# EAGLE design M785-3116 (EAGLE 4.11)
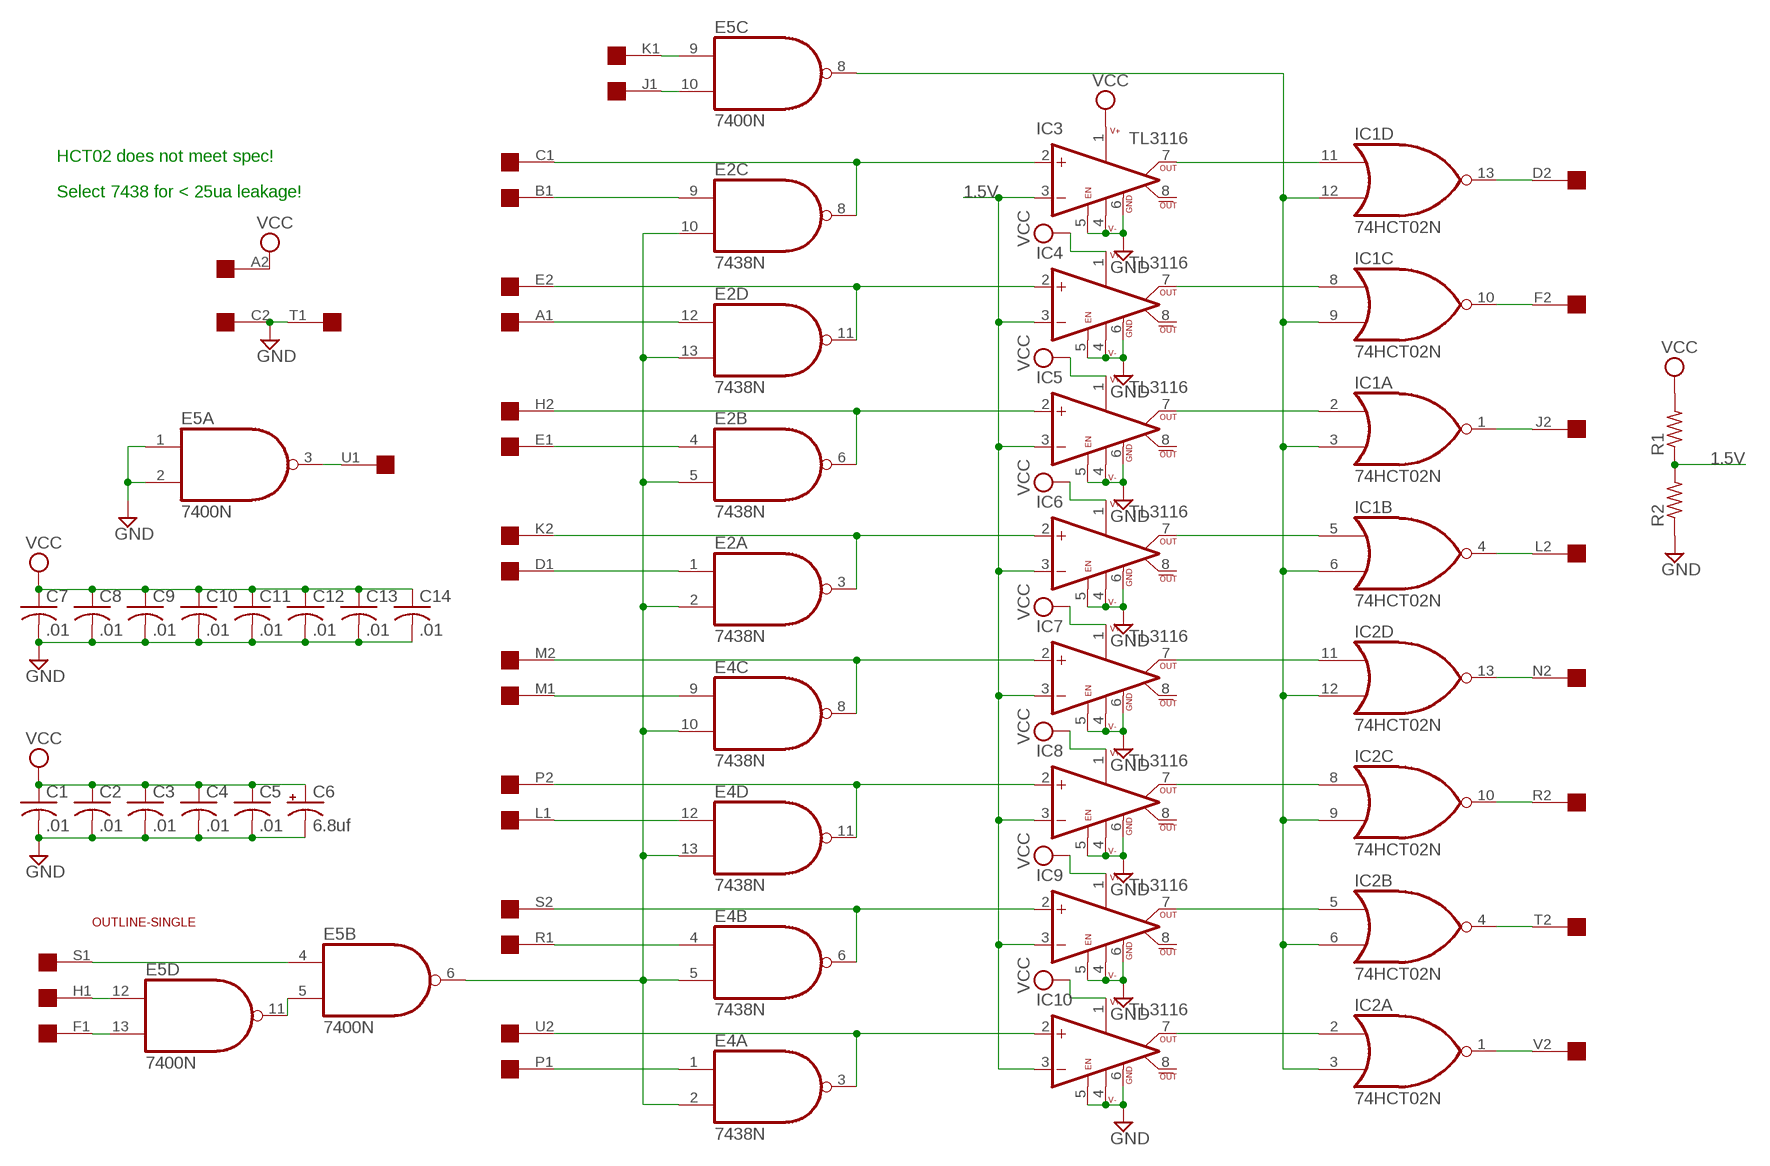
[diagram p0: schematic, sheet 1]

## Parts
C1  .01  C-US050-025X075  [C050-025X075]
C2  .01  C-US050-025X075  [C050-025X075]
C3  .01  C-US050-025X075  [C050-025X075]
C4  .01  C-US050-025X075  [C050-025X075]
C5  .01  C-US050-025X075  [C050-025X075]
C6  6.8uf  CPOL-USE15-5AXIAL  [E15-5]
C7  .01  C-US050-025X075  [C050-025X075]
C8  .01  C-US050-025X075  [C050-025X075]
C9  .01  C-US050-025X075  [C050-025X075]
C10  .01  C-US050-025X075  [C050-025X075]
C11  .01  C-US050-025X075  [C050-025X075]
C12  .01  C-US050-025X075  [C050-025X075]
C13  .01  C-US050-025X075  [C050-025X075]
C14  .01  C-US050-025X075  [C050-025X075]
E2  7438N  [DIL14]
E4  7438N  [DIL14]
E5  7400N  [DIL14]
IC1  74HCT02N  7402N  [DIL14]
IC2  74HCT02N  7402N  [DIL14]
IC3  TL3116  LT1016CN  [DIL08]
IC4  TL3116  LT1016CN  [DIL08]
IC5  TL3116  LT1016CN  [DIL08]
IC6  TL3116  LT1016CN  [DIL08]
IC7  TL3116  LT1016CN  [DIL08]
IC8  TL3116  LT1016CN  [DIL08]
IC9  TL3116  LT1016CN  [DIL08]
IC10  TL3116  LT1016CN  [DIL08]
R1  R-US_0207/10  [0207/10]
R2  R-US_0207/10  [0207/10]
U$1  SINGLE  [EDGE-CON2]
U$2  OUTLINE-SINGLE  [SINGLE]

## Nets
1.5V: IC3.3(-IN) IC4.3(-IN) IC5.3(-IN) IC6.3(-IN) IC7.3(-IN) IC8.3(-IN) IC9.3(-IN) IC10.3(-IN) R1.1 R2.2
GND: C1.2 C2.2 C3.2 C4.2 C5.2 C6.- C7.2 C8.2 C9.2 C10.2 C11.2 C12.2 C13.2 C14.2 E5.1(A:I0) E5.2(A:I1) IC3.4(V-) IC3.5(LA_EN) IC3.6(GND) IC4.4(V-) IC4.5(LA_EN) IC4.6(GND) IC5.4(V-) IC5.5(LA_EN) IC5.6(GND) IC6.4(V-) IC6.5(LA_EN) IC6.6(GND) IC7.4(V-) IC7.5(LA_EN) IC7.6(GND) IC8.4(V-) IC8.5(LA_EN) IC8.6(GND) IC9.4(V-) IC9.5(LA_EN) IC9.6(GND) IC10.4(V-) IC10.5(LA_EN) IC10.6(GND) R2.1 U$1.C2 U$1.T1
N$1: E5.8(C:O) IC1.3(A:I1) IC1.6(B:I1) IC1.9(C:I1) IC1.12(D:I1) IC2.3(A:I1) IC2.6(B:I1) IC2.9(C:I1) IC2.12(D:I1)
N$2: E2.2(A:I1) E2.5(B:I1) E2.10(C:I1) E2.13(D:I1) E4.2(A:I1) E4.5(B:I1) E4.10(C:I1) E4.13(D:I1) E5.6(B:O)
N$3: E4.8(C:O) IC7.2(+IN) U$1.M2
N$4: E4.3(A:O) IC10.2(+IN) U$1.U2
N$5: E4.1(A:I0) U$1.P1
N$6: E4.4(B:I0) U$1.R1
N$7: E4.6(B:O) IC9.2(+IN) U$1.S2
N$8: E4.12(D:I0) U$1.L1
N$9: E4.11(D:O) IC8.2(+IN) U$1.P2
N$10: E4.9(C:I0) U$1.M1
N$11: E2.8(C:O) IC3.2(+IN) U$1.C1
N$12: E2.9(C:I0) U$1.B1
N$13: E2.11(D:O) IC4.2(+IN) U$1.E2
N$14: E2.12(D:I0) U$1.A1
N$15: E2.6(B:O) IC5.2(+IN) U$1.H2
N$16: E2.4(B:I0) U$1.E1
N$17: E2.3(A:O) IC6.2(+IN) U$1.K2
N$18: E2.1(A:I0) U$1.D1
N$19: E5.9(C:I0) U$1.K1
N$20: E5.10(C:I1) U$1.J1
N$21: IC1.13(D:O) U$1.D2
N$22: IC1.10(C:O) U$1.F2
N$23: IC1.1(A:O) U$1.J2
N$24: IC1.4(B:O) U$1.L2
N$25: IC2.13(D:O) U$1.N2
N$26: IC2.10(C:O) U$1.R2
N$27: IC2.4(B:O) U$1.T2
N$28: IC2.1(A:O) U$1.V2
N$29: E5.4(B:I0) U$1.S1
N$30: E5.5(B:I1) E5.11(D:O)
N$31: E5.12(D:I0) U$1.H1
N$32: E5.13(D:I1) U$1.F1
N$33: E5.3(A:O) U$1.U1
N$34: IC1.11(D:I0) IC3.7(OUT)
N$35: IC2.11(D:I0) IC7.7(OUT)
N$36: IC1.5(B:I0) IC6.7(OUT)
N$37: IC1.2(A:I0) IC5.7(OUT)
N$38: IC1.8(C:I0) IC4.7(OUT)
N$39: IC2.5(B:I0) IC9.7(OUT)
N$40: IC2.8(C:I0) IC8.7(OUT)
N$43: IC2.2(A:I0) IC10.7(OUT)
VCC: C1.1 C2.1 C3.1 C4.1 C5.1 C6.+ C7.1 C8.1 C9.1 C10.1 C11.1 C12.1 C13.1 C14.1 IC3.1(V+) IC4.1(V+) IC5.1(V+) IC6.1(V+) IC7.1(V+) IC8.1(V+) IC9.1(V+) IC10.1(V+) R1.2 U$1.A2
Unconnected: IC3.8(OUT\) IC4.8(OUT\) IC5.8(OUT\) IC6.8(OUT\) IC7.8(OUT\) IC8.8(OUT\) IC9.8(OUT\) IC10.8(OUT\) U$1.B2 U$1.N1 U$1.V1

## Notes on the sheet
- HCT02 does not meet spec!
- Select 7438 for < 25ua leakage!

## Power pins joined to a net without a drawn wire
GND: E2.7(P:GND) E4.7(P:GND) E5.7(P:GND) IC1.7(P:GND) IC2.7(P:GND)
VCC: E2.14(P:VCC) E4.14(P:VCC) E5.14(P:VCC) IC1.14(P:VCC) IC2.14(P:VCC)

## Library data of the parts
C1-C5 C7-C14 = rcl:C-US: CAPACITOR, American symbol
C6 = rcl:CPOL-US: POLARIZED CAPACITOR, American symbol
E2 E4 = 74xx-jameco:74*38: Quad 2-input NAND gate, open collector output
E5 = 74xx-jameco:74*00: Quad 2-input NAND gate
IC1 IC2 = 74xx-jameco:74*02: Quad 2-input NOR gate
IC3-IC10 = linear-technology:LT1016: Ultra-fast precision COMPARATOR
R1 R2 = rcl:R-US_: RESISTOR, American symbol
U$1 = dec-con:SINGLE: Single-Height DEC board
U$2 = dec-con:OUTLINE-*: Board outlines for DEC boards.

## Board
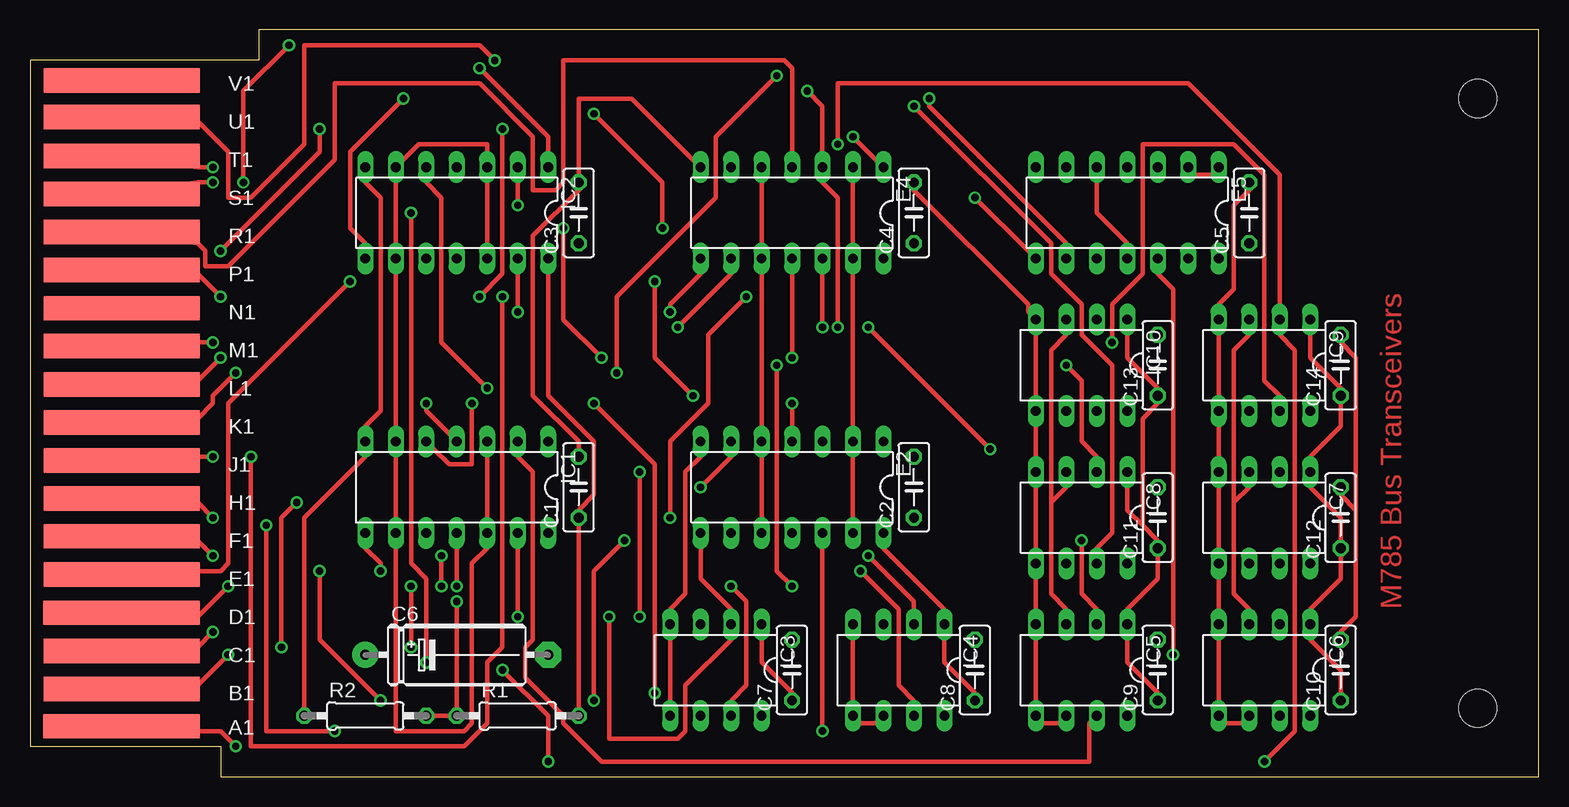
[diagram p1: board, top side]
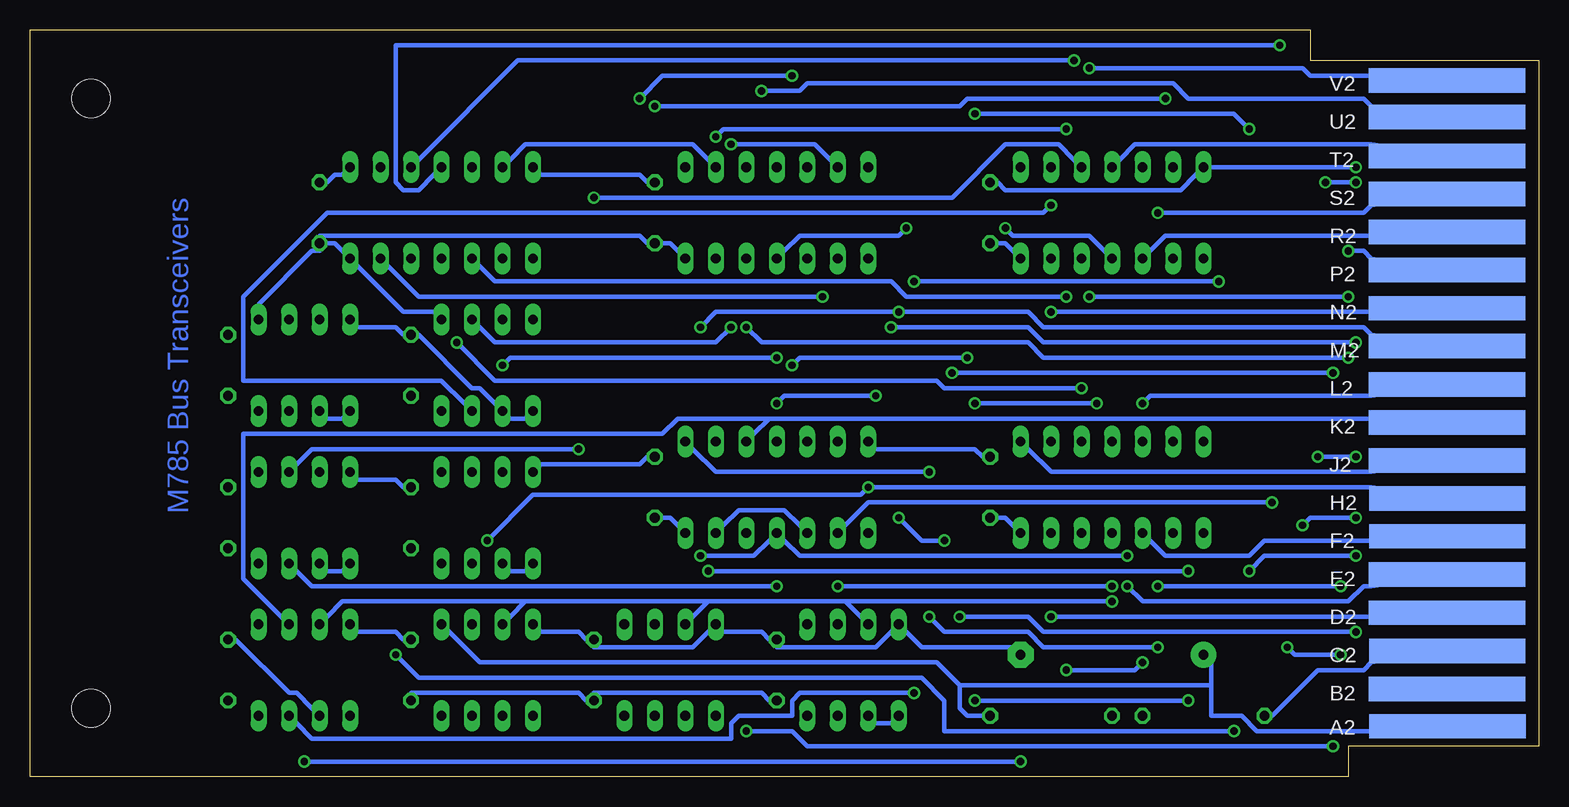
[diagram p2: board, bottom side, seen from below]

Size 125.73 x 62.23 mm. Coordinates in mm from the lower left corner, seen from the top.
Copper layers (1*16): Top 0.035mm / dielectric 1.5mm / Bottom 0.035mm
Design rules "15mils": minimum track width 15mil, minimum drill 24mil, track to track 15mil, track to pad 10mil, pad to pad 10mil, via to via 10mil, smd to smd 10mil, copper to edge 25mil, drill to drill 10mil, minimum pad ring 10mil, minimum via ring 8mil, stop-mask expansion 0mil, vias tented up to drill 0mil, thermal gap 10mil

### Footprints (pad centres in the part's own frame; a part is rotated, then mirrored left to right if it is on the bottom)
C050-025X075 = drill 0.813 octagon: 1 -2.54,0; 2 2.54,0
E15-5 = drill 0.813 pad 2.159 round: + -7.62,0 | drill 0.813 pad 2.159 octagon: - 7.62,0
DIL14 = drill 0.813 long: 1 -7.62,-3.81; 2 -5.08,-3.81; 3 -2.54,-3.81; 4 0,-3.81; 5 2.54,-3.81; 6 5.08,-3.81; 7 7.62,-3.81; 8 7.62,3.81; 9 5.08,3.81; 10 2.54,3.81; 11 0,3.81; 12 -2.54,3.81; 13 -5.08,3.81; 14 -7.62,3.81
DIL08 = drill 0.813 long: 1 -3.81,-3.81; 2 -1.27,-3.81; 3 1.27,-3.81; 4 3.81,-3.81; 5 3.81,3.81; 6 1.27,3.81; 7 -1.27,3.81; 8 -3.81,3.81
0207/10 = drill 0.813 octagon: 1 -5.08,0; 2 5.08,0
EDGE-CON2 = smd 13.017 x 2.032: A1 7.633,4.207; B1 7.639,7.327; C1 7.636,10.489; D1 7.633,13.665; E1 7.642,16.84; F1 7.642,20.041; H1 7.642,23.19; J1 7.642,26.34; K1 7.642,29.515; L1 7.642,32.69; M1 7.642,35.89; N1 7.642,39.04; P1 7.642,42.24; R1 7.642,45.39; S1 7.642,48.565; T1 7.642,51.74; U1 7.642,54.966; V1 7.642,58.026 | smd 13.017 x 2.032 bottom: A2 7.614,4.207; B2 7.642,7.328; C2 7.617,10.49; D2 7.642,13.665; E2 7.642,16.84; F2 7.617,20.041; H2 7.617,23.19; J2 7.642,26.34; K2 7.642,29.515; L2 7.642,32.69; M2 7.642,35.89; N2 7.642,39.04; P2 7.642,42.24; R2 7.642,45.39; S2 7.642,48.565; T2 7.642,51.74; U2 7.642,54.966; V2 7.642,58.026
SINGLE = hole 3.175: 120.65,56.515; 120.65,5.715

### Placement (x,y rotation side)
C1  45.72,24.13 90 top
C2  73.66,24.13 90 top
C3  45.72,46.99 90 top
C4  73.66,46.99 90 top
C5  101.6,46.99 90 top
C6  35.56,10.16 0 top
C7  63.5,8.89 90 top
C8  78.74,8.89 90 top
C9  93.98,8.89 90 top
C10  109.22,8.89 90 top
C11  93.98,21.59 90 top
C12  109.22,21.59 90 top
C13  93.98,34.29 90 top
C14  109.22,34.29 90 top
E2  63.5,24.13 180 top
E4  63.5,46.99 180 top
E5  91.44,46.99 180 top
IC1  35.56,24.13 180 top
IC2  35.56,46.99 180 top
IC3  57.15,8.89 180 top
IC4  72.39,8.89 180 top
IC5  87.63,8.89 180 top
IC6  102.87,8.89 180 top
IC7  102.87,21.59 180 top
IC8  87.63,21.59 180 top
IC9  102.87,34.29 180 top
IC10  87.63,34.29 180 top
R1  40.64,5.08 0 top
R2  27.94,5.08 0 top
U$1  0,0 0 top
U$2  0,0 0 top

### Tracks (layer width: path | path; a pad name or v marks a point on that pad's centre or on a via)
1.5V  (via drill 0.61)
  Top 0.381: R2.2 33.66,5.08 34.93,5.08 R1.1 35.56,5.71 v35.56,14.61 | 85.09,22.86 86.36,24.13 IC8.3 | 85.09,22.86 85.09,15.24 86.36,13.97 IC5.3 | 85.09,22.86 85.09,35.56 86.36,36.83 IC10.3 | 100.33,22.86 101.6,24.13 IC7.3 | 100.33,22.86 100.33,15.24 101.6,13.97 IC6.3 | 100.33,22.86 100.33,35.56 101.6,36.83 IC9.3
  Bottom 0.381: 57.79,14.61 56.52,13.34 IC3.3 | 57.79,14.61 69.22,14.61 | 69.22,14.61 70.49,13.34 IC4.3 | 84.46,14.61 85.73,13.34 IC5.3 | 69.22,14.61 84.46,14.61 | 84.46,14.61 99.7,14.61 100.97,13.34 IC6.3 | v35.56,14.61 57.79,14.61
GND  (via drill 0.61)
  Top 0.381: R2.1 22.86,5.71 22.86,21.59 27.94,26.67 IC1.7 27.94,29.21 29.21,30.48 29.21,48.26 27.94,49.53 IC2.7 | E4.7 55.25,51.44 50.17,56.52 45.72,56.52 45.72,50.16 C3.2 45.72,48.9 41.91,45.09 41.91,31.75 45.72,27.94 45.72,27.3 C1.2 | v15.24,50.8 13.97,50.8 U$1.T1 | IC6.6 100.97,4.45 99.7,4.45 IC6.5 99.06,6.35 99.06,11.43 IC6.4 99.06,13.97 99.06,16.51 IC7.5 99.06,19.05 99.06,24.13 IC7.4 99.06,26.67 99.06,29.21 IC9.5 99.06,31.75 99.06,36.83 IC9.4 99.06,39.37 100.33,40.64 100.33,47.62 101.6,48.9 C5.2 | 110.49,22.23 109.22,23.5 C12.2 | 110.49,22.23 110.49,13.34 109.22,12.06 C10.2 | 110.49,22.23 110.49,34.92 109.22,36.2 C14.2 | E5.2 97.16,50.16 98.43,50.16 E5.1 | IC3.5 53.34,6.35 53.34,11.43 IC3.4 53.34,13.97 54.61,15.24 54.61,25.4 55.88,26.67 E2.7 | IC4.6 70.49,4.45 69.22,4.45 IC4.5 68.58,6.35 68.58,11.43 IC4.4 | IC5.6 85.73,4.45 84.46,4.45 IC5.5 83.82,6.35 83.82,11.43 IC5.4 83.82,13.97 83.82,16.51 IC8.5 83.82,19.05 83.82,24.13 IC8.4 83.82,26.67 83.82,29.21 IC10.5 83.82,31.75 83.82,36.83 IC10.4 83.19,38.73 83.19,39.37 73.66,48.9 C4.2
  Bottom 0.381: R2.1 22.23,5.08 18.42,8.89 14.61,8.89 13.97,9.53 U$1.C2 | C3.2 45.09,49.53 44.45,48.9 29.85,48.9 28.58,50.16 IC2.7 27.31,50.8 v15.24,50.8 | C10.2 108.59,11.43 104.14,6.99 103.51,6.99 102.24,5.71 IC6.6 | IC7.5 99.7,17.14 100.97,17.14 IC7.6 | C9.2 94.62,11.43 95.25,12.06 98.43,12.06 IC6.4 | C5.2 100.97,49.53 100.33,50.16 99.7,50.16 E5.1 | IC9.4 98.43,37.47 95.25,37.47 94.62,36.83 C13.2 93.35,36.83 88.9,32.38 88.27,32.38 87,31.11 IC10.6 85.73,29.84 84.46,29.84 IC10.5 | IC9.5 99.7,29.84 100.97,29.84 IC9.6 | C11.2 94.62,24.13 95.25,24.77 98.43,24.77 IC7.4 | C1.2 46.36,26.67 46.99,27.3 55.25,27.3 E2.7 | IC3.5 53.98,4.45 55.25,4.45 IC3.6 | C6.- 43.82,10.79 51.44,10.79 52.71,12.06 IC3.4 53.98,12.06 55.25,10.79 63.5,10.79 C7.2 64.14,11.43 64.77,12.06 67.95,12.06 IC4.4 69.22,12.06 70.49,10.79 78.74,10.79 C8.2 79.38,11.43 80.01,12.06 83.19,12.06 IC5.4 | IC8.5 84.46,17.14 85.73,17.14 IC8.6 | C4.2 74.3,49.53 74.93,50.16 83.19,50.16 E5.7 | C2.2 74.3,26.67 74.93,26.04 83.19,26.04 IC8.4
N$1  (via drill 0.61)
  Top 0.381: IC1.3 38.1,26.67 38.1,21.59 IC1.12 38.1,19.05 36.83,17.78 36.83,4.45 36.2,3.81 30.48,3.81 30.48,19.05 IC1.9 30.48,21.59 30.48,26.67 IC1.6 30.48,29.21 30.48,41.91 IC2.9 30.48,44.45 30.48,49.53 IC2.6 31.12,51.44 32.39,52.7 38.1,52.7 38.1,52.07 IC2.3 38.1,49.53 38.1,44.45 IC2.12 | v78.74,48.26 83.19,43.81 E5.8
  Bottom 0.381: v78.74,48.26 48.9,48.26 44.45,52.7 40.01,52.7 38.74,51.44 IC2.3
N$2
  Top 0.381: E2.10 60.96,21.59 60.96,26.67 E2.5 60.96,29.21 60.96,41.91 E4.10 60.96,44.45 60.96,49.53 E4.5 | E2.13 68.58,21.59 68.58,26.67 E2.2 68.58,29.21 68.58,41.91 E4.13 68.58,44.45 68.58,49.53 E4.2
  Bottom 0.381: E5.6 85.73,51.44 84.46,52.7 70.49,52.7 69.22,51.44 E4.2 | E2.10 61.6,20.95 62.87,22.23 66.68,22.23 67.95,20.95 E2.13
N$3  (via drill 0.61)
  Top 0.381: v53.34,38.73 53.34,39.37 55.88,41.91 E4.8 | v69.85,37.47 v80.01,27.3
  Bottom 0.381: U$1.M2 13.97,36.83 14.61,37.47 41.28,37.47 42.55,38.73 v53.34,38.73 68.58,38.73 v69.85,37.47 | v80.01,27.3 102.24,27.3 103.51,26.04 IC7.2
N$4  (via drill 0.61)
  Top 0.381: v67.31,37.47 67.31,48.26 66.04,49.53 E4.3 66.04,52.07 66.04,55.88 v64.77,57.15
  Bottom 0.381: v67.31,37.47 68.58,36.2 87,36.2 88.27,37.47 IC10.2 | v64.77,57.15 61.6,57.15 60.96,57.78 30.48,57.78 29.21,56.52 14.61,56.52 13.97,55.88 U$1.U2
N$5  (via drill 0.61)
  Top 0.381: v68.58,53.34 70.49,51.44 E4.1 | v39.37,53.98 39.37,41.91 v37.47,40.01 | v15.88,40.01 13.97,41.91 U$1.P1
  Bottom 0.381: v68.58,53.34 67.95,53.98 v39.37,53.98 | v15.88,40.01 v37.47,40.01
N$6
  Top 0.381: E4.4 63.5,52.07 63.5,59.05 62.87,59.69 44.45,59.69 44.45,49.53 43.82,48.9 41.91,48.9 41.91,53.34 37.47,57.78 25.4,57.78 25.4,51.44 16.51,42.55 14.61,42.55 14.61,43.81 13.97,44.45 U$1.R1
N$7  (via drill 0.61)
  Top 0.381: v67.31,52.7 67.31,57.78 96.52,57.78 104.14,50.16 104.14,39.37 IC9.2 104.14,36.83 105.41,35.56 105.41,3.81 v102.87,1.27 | v31.75,46.99 31.75,17.78 33.02,16.51 v33.02,9.53 | v39.37,8.89 43.18,5.08 v43.18,1.27
  Bottom 0.381: v67.31,52.7 60.33,52.7 59.06,51.44 E4.6 | v31.75,46.99 14.61,46.99 13.97,47.62 U$1.S2 | v33.02,9.53 33.66,8.89 v39.37,8.89 | v43.18,1.27 v102.87,1.27
N$8  (via drill 0.61)
  Top 0.381: v66.04,37.47 66.04,41.91 E4.12 | v15.88,34.92 13.97,33.02 U$1.L1
  Bottom 0.381: v66.04,37.47 64.77,36.2 42.55,36.2 41.28,34.92 v15.88,34.92
N$9  (via drill 0.61)
  Top 0.381: v86.36,34.29 87.63,33.02 87.63,27.94 88.9,26.67 IC8.2 | v63.5,34.92 63.5,41.91 E4.11 | v15.88,43.81 24.13,52.07 v24.13,53.98 | v46.99,55.24 52.71,49.53 v52.71,45.72
  Bottom 0.381: v86.36,34.29 85.73,34.92 v63.5,34.92 | v15.88,43.81 14.61,43.81 13.97,43.18 U$1.P2 | v24.13,53.98 25.4,55.24 v46.99,55.24 | v52.71,45.72 53.34,45.09 61.6,45.09 62.87,43.81 E4.11
N$10  (via drill 0.61)
  Top 0.381: v53.98,37.47 58.42,41.91 E4.9 | v15.24,36.2 13.97,36.2 U$1.M1
  Bottom 0.381: v53.98,37.47 42.55,37.47 41.28,36.2 v15.24,36.2
N$11  (via drill 0.61)
  Top 0.381: E2.8 55.88,19.05 55.88,16.51 58.42,13.97 IC3.2 58.42,11.43 54.61,7.62 54.61,3.81 53.98,3.17 48.26,3.17 v48.26,13.34 | v15.24,12.06 13.97,10.79 U$1.C1
  Bottom 0.381: v48.26,13.34 42.55,13.34 41.28,12.06 v15.24,12.06
N$12  (via drill 0.61)
  Top 0.381: v22.23,22.86 20.96,21.59 v20.96,10.79 | v16.51,10.16 13.97,7.62 U$1.B1
  Bottom 0.381: v22.23,22.86 55.88,22.86 57.79,20.95 E2.9 | v20.96,10.79 20.32,10.16 v16.51,10.16
N$13  (via drill 0.61)
  Top 0.381: v69.85,18.41 73.66,14.61 73.66,13.97 IC4.2 | v34.29,15.88 v34.29,18.41
  Bottom 0.381: v69.85,18.41 65.41,18.41 64.14,19.68 E2.11 62.87,19.68 61.6,18.41 v34.29,18.41 | v34.29,15.88 33.02,14.61 15.88,14.61 14.61,15.88 13.97,15.88 U$1.E2
N$14  (via drill 0.61)
  Top 0.381: v66.04,3.81 66.04,19.05 E2.12 | v17.15,2.54 15.88,3.81 13.97,3.81 U$1.A1
  Bottom 0.381: v66.04,3.81 62.23,3.81 60.96,2.54 v17.15,2.54
N$15  (via drill 0.61)
  Top 0.381: v55.88,24.13 58.42,26.67 E2.6 | v87.63,19.68 87.63,15.24 88.9,13.97 IC5.2
  Bottom 0.381: U$1.H2 13.97,24.13 v55.88,24.13 56.52,23.5 83.82,23.5 v87.63,19.68
N$16  (via drill 0.61)
  Top 0.381: v63.5,31.11 63.5,29.21 E2.4 | v55.25,31.75 52.07,34.92 v52.07,41.27 | v26.67,41.27 16.51,31.11 16.51,17.78 15.88,17.14 13.97,17.14 U$1.E1
  Bottom 0.381: v63.5,31.11 62.87,31.75 v55.25,31.75 | v26.67,41.27 v52.07,41.27
N$17
  Bottom 0.381: 64.14,29.84 65.41,28.57 E2.3 | 64.14,29.84 13.97,29.84 U$1.K2 | 64.14,29.84 71.76,29.84 73.03,28.57 107.95,28.57 107.95,16.51 104.78,13.34 IC6.2
N$18  (via drill 0.61)
  Top 0.381: v50.8,13.34 v50.8,25.4 | v31.75,15.88 v31.75,10.79 | v16.51,15.88 13.97,13.34 U$1.D1
  Bottom 0.381: v50.8,25.4 68.58,25.4 70.49,27.3 E2.1 | v50.8,13.34 49.53,12.06 42.55,12.06 41.28,10.79 v31.75,10.79 | v16.51,15.88 v31.75,15.88
N$19  (via drill 0.61)
  Top 0.381: v74.93,56.52 74.93,55.88 86.36,44.45 E5.9 | v62.23,58.42 57.15,53.34 57.15,48.26 48.9,40.01 v48.9,33.66 | v17.15,33.66 15.24,31.75 15.24,31.11 13.97,29.84 U$1.K1
  Bottom 0.381: v74.93,56.52 73.03,58.42 v62.23,58.42 | v17.15,33.66 v48.9,33.66
N$20  (via drill 0.61)
  Top 0.381: v39.37,40.01 39.37,10.79 38.1,9.53 38.1,4.45 36.2,2.54 18.42,2.54 v18.42,26.67 | v15.24,26.67 13.97,26.67 U$1.J1
  Bottom 0.381: v39.37,40.01 52.71,40.01 53.98,41.27 87,41.27 88.27,42.55 E5.10 | v18.42,26.67 v15.24,26.67
N$21  (via drill 0.61)
  Top 0.381: v40.64,13.34 40.64,19.05 IC1.13
  Bottom 0.381: v40.64,13.34 13.97,13.34 U$1.D2
N$22
  Bottom 0.381: IC1.10 32.39,19.68 31.12,18.41 24.13,18.41 22.86,19.68 13.97,19.68 U$1.F2
N$23
  Bottom 0.381: IC1.1 42.55,27.3 40.64,25.4 13.97,25.4 U$1.J2
N$24  (via drill 0.61)
  Top 0.381: v33.02,31.11 33.02,30.48 34.93,28.57 IC1.4
  Bottom 0.381: v33.02,31.11 32.39,31.75 13.97,31.75 U$1.L2
N$25  (via drill 0.61)
  Top 0.381: v40.64,38.73 40.64,41.91 IC2.13
  Bottom 0.381: v40.64,38.73 13.97,38.73 U$1.N2
N$26
  Bottom 0.381: IC2.10 32.39,43.81 31.12,45.09 13.97,45.09 U$1.R2
N$27
  Bottom 0.381: IC2.4 34.93,51.44 33.66,52.7 13.97,52.7 U$1.T2
N$28  (via drill 0.61)
  Top 0.381: v37.47,59.05 43.18,53.34 43.18,52.07 IC2.1
  Bottom 0.381: v37.47,59.05 19.69,59.05 19.05,58.42 13.97,58.42 U$1.V2
N$29  (via drill 0.61)
  Top 0.381: v21.59,60.96 17.78,57.15 v17.78,49.53 | v15.24,49.53 13.97,49.53 U$1.S1
  Bottom 0.381: v21.59,60.96 95.25,60.96 95.25,49.53 94.62,48.9 93.35,48.9 92.08,50.16 E5.4 | v15.24,49.53 v17.78,49.53
N$30
  Top 0.381: E5.11 91.44,44.45 88.9,46.99 88.9,49.53 E5.5
N$31  (via drill 0.61)
  Top 0.381: v95.25,10.16 95.25,40.64 93.98,41.91 E5.12 | v25.4,3.81 19.69,3.81 v19.69,20.95 | v15.24,21.59 13.97,22.86 U$1.H1
  Bottom 0.381: v95.25,10.16 93.35,8.26 51.44,8.26 49.53,6.35 49.53,3.81 v25.4,3.81 | v19.69,20.95 19.05,21.59 v15.24,21.59
N$32  (via drill 0.61)
  Top 0.381: v59.69,40.01 56.52,36.83 56.52,31.11 53.34,27.94 v53.34,21.59 | v49.53,19.68 46.99,17.14 v46.99,6.35 | v29.21,6.35 24.13,11.43 v24.13,17.14 | v15.24,18.41 13.97,19.68 U$1.F1
  Bottom 0.381: v59.69,40.01 93.35,40.01 95.89,42.55 E5.13 | v53.34,21.59 51.44,19.68 v49.53,19.68 | v29.21,6.35 v46.99,6.35 | v24.13,17.14 22.86,18.41 v15.24,18.41
N$33  (via drill 0.61)
  Top 0.381: v38.74,59.69 37.47,60.96 22.86,60.96 22.86,52.7 18.42,48.26 16.51,48.26 16.51,52.07 13.97,54.61 U$1.U1
  Bottom 0.381: v38.74,59.69 85.09,59.69 93.35,51.44 E5.3
N$34  (via drill 0.61)
  Top 0.381: v35.56,15.88 35.56,19.05 IC1.11 | v58.42,15.88 59.69,14.61 59.69,7.62 58.42,6.35 IC3.7
  Bottom 0.381: v35.56,15.88 v58.42,15.88
N$35  (via drill 0.61)
  Top 0.381: v63.5,15.88 62.23,17.14 v62.23,34.29 | v47.63,34.92 44.45,38.1 v44.45,45.72
  Bottom 0.381: v63.5,15.88 102.24,15.88 103.51,17.14 IC7.7 | v62.23,34.29 61.6,34.92 v47.63,34.92 | v44.45,45.72 43.82,45.09 37.47,45.09 36.2,43.81 IC2.11
N$36  (via drill 0.61)
  Top 0.381: v36.83,31.11 36.83,26.04 34.93,26.04 33.66,27.3 IC1.5 | v46.99,31.11 52.07,26.04 v52.07,6.99
  Bottom 0.381: v46.99,31.11 v36.83,31.11 | v52.07,6.99 61.6,6.99 62.23,6.35 62.23,5.08 66.68,5.08 67.31,4.45 67.31,3.17 102.24,3.17 103.51,4.45 IC6.7
N$37
  Top 0.381: IC1.2 40.64,26.67 41.91,25.4 41.91,11.43 41.28,10.79 41.28,8.26 44.45,5.08 44.45,4.45 47.63,1.27 88.27,1.27 88.27,4.45 IC5.7
N$38  (via drill 0.61)
  Top 0.381: v29.21,17.14 29.21,17.78 27.94,19.05 IC1.8 | v69.22,17.14 72.39,13.97 72.39,7.62 73.66,6.35 IC4.7
  Bottom 0.381: v29.21,17.14 v69.22,17.14
N$39  (via drill 0.61)
  Top 0.381: v90.17,36.2 90.17,39.37 92.71,41.91 92.71,52.7 100.33,52.7 102.87,50.16 102.87,33.02 104.14,31.75 IC9.7 | v38.1,32.38 34.29,36.2 34.29,48.26 33.02,49.53 IC2.5
  Bottom 0.381: v90.17,36.2 87,33.02 50.17,33.02 49.53,32.38 v38.1,32.38
N$40  (via drill 0.61)
  Top 0.381: v73.66,55.88 85.09,44.45 85.09,41.91 87.63,39.37 87.63,36.83 90.17,34.29 90.17,20.32 88.9,19.05 IC8.7 | v31.12,56.52 26.67,52.07 26.67,45.72 27.94,44.45 IC2.8
  Bottom 0.381: v73.66,55.88 48.26,55.88 47.63,56.52 v31.12,56.52
N$43  (via drill 0.61)
  Top 0.381: v40.64,47.62 40.64,49.53 IC2.2
  Bottom 0.381: v40.64,47.62 41.28,46.99 100.97,46.99 107.95,40.01 107.95,33.02 91.44,33.02 89.54,31.11 IC10.7
VCC
  Top 0.381: C7.1 63.5,6.99 60.96,9.53 60.96,11.43 IC3.1 | C8.1 78.74,6.99 76.2,9.53 76.2,11.43 IC4.1 76.2,13.97 71.12,19.05 E2.14 | IC10.1 91.44,36.83 91.44,34.92 93.98,32.38 C13.1 93.98,31.11 92.71,29.84 92.71,20.95 | C9.1 93.98,6.99 91.44,9.53 91.44,11.43 IC5.1 91.44,13.97 93.98,16.51 93.98,18.41 C11.1 93.98,19.68 92.71,20.95 | 92.71,20.95 91.44,22.23 91.44,24.13 IC8.1 | C10.1 109.22,6.99 109.22,8.89 106.68,11.43 IC6.1 106.68,13.97 109.22,16.51 109.22,18.41 C12.1 109.22,19.68 109.22,21.59 106.68,24.13 IC7.1 106.68,26.67 109.22,29.21 109.22,31.11 C14.1 109.22,32.38 106.68,34.92 106.68,36.83 IC9.1 | R1.2 45.72,5.71 45.72,20.95 C1.1 45.72,22.23 46.99,23.5 46.99,27.94 43.18,31.75 43.18,41.91 IC2.14
  Bottom 0.381: E2.14 71.76,20.95 72.39,21.59 73.03,21.59 C2.1 | C7.1 64.14,6.35 64.77,6.99 78.74,6.99 C8.1 79.38,6.35 80.01,6.99 93.98,6.99 C9.1 | E4.14 71.76,43.81 72.39,44.45 73.03,44.45 C4.1 74.3,44.45 74.93,45.09 101.6,45.09 C5.1 | C5.1 100.97,44.45 100.33,44.45 99.7,43.81 E5.14 98.43,42.55 94.62,38.73 92.08,38.73 IC10.1 | IC9.1 106.68,39.37 102.24,43.81 101.6,43.81 C5.1 | IC2.14 43.82,43.81 44.45,44.45 45.09,44.45 C3.1 | IC1.14 43.82,20.95 44.45,21.59 45.09,21.59 C1.1 | 27.31,7.62 27.31,5.08 24.77,5.08 23.5,3.81 13.97,3.81 U$1.A2 | 27.31,7.62 27.31,9.53 C6.+ | 48.26,7.62 48.26,5.71 47.63,5.08 46.36,5.08 R1.2 | 27.31,7.62 48.26,7.62 | 48.26,7.62 50.17,9.53 88.27,9.53 90.81,12.06 IC5.1

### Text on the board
Top: M785 Bus Transceivers
Bottom: M785 Bus Transceivers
